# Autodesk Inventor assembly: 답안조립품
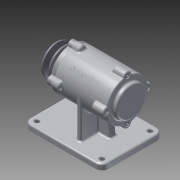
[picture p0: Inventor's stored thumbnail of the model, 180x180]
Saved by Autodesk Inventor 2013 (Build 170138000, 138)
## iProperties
Created: 2015-12
Part Number: 답안조립품
Document SubType Name: Assembly
Designer: hana
Author: hana
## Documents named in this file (11)
- C:\Documents and Settings\hana\바탕 화면\451208V1019\답안조립품.iam
- C:\Documents and Settings\hana\바탕 화면\451208V1019\1.본체.ipt
- C:\Documents and Settings\hana\바탕 화면\451208V1019\커버2.ipt
- C:\Documents and Settings\hana\바탕 화면\451208V1019\커버.ipt
- C:\Documents and Settings\hana\바탕 화면\451208V1019\베어링 6204.ipt
- C:\Documents and Settings\hana\바탕 화면\451208V1019\축.ipt
- C:\Documents and Settings\hana\바탕 화면\451208V1019\오일실.ipt
- C:\Documents and Settings\hana\바탕 화면\451208V1019\V-벨트풀리.ipt
- C:\Documents and Settings\hana\바탕 화면\451208V1019\키(4 x 4 x 12).ipt
- C:\Documents and Settings\hana\바탕 화면\451208V1019\너트 M12x1.25.ipt
- C:\Documents and Settings\hana\바탕 화면\451208V1019\볼트 M4 x 12.ipt
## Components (7 placed, 6 different names)
1. 1.본체:1
2. KS B 2023 6204 - 20 x 47 x 14:1
3. KS B 2023 6204 - 20 x 47 x 14:2
4. KS B 2804 D D - 20 32 8:1
5. V-벨트풀리:1 — 각도:2, 각도:3
6. KS B 1311 (I) 4 x 4 x 12:1 — 각도:1, 각도:2
7. KS B 1012 클래스 1 일반 - 미터 M12x1.25:1 — 각도:3
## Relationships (3: Angle 3)
- 각도:1 [Angle]: KS B 1311 (I) 4 x 4 x 12:1
- 각도:2 [Angle]: V-벨트풀리:1 ↔ KS B 1311 (I) 4 x 4 x 12:1
- 각도:3 [Angle]: V-벨트풀리:1 ↔ KS B 1012 클래스 1 일반 - 미터 M12x1.25:1
